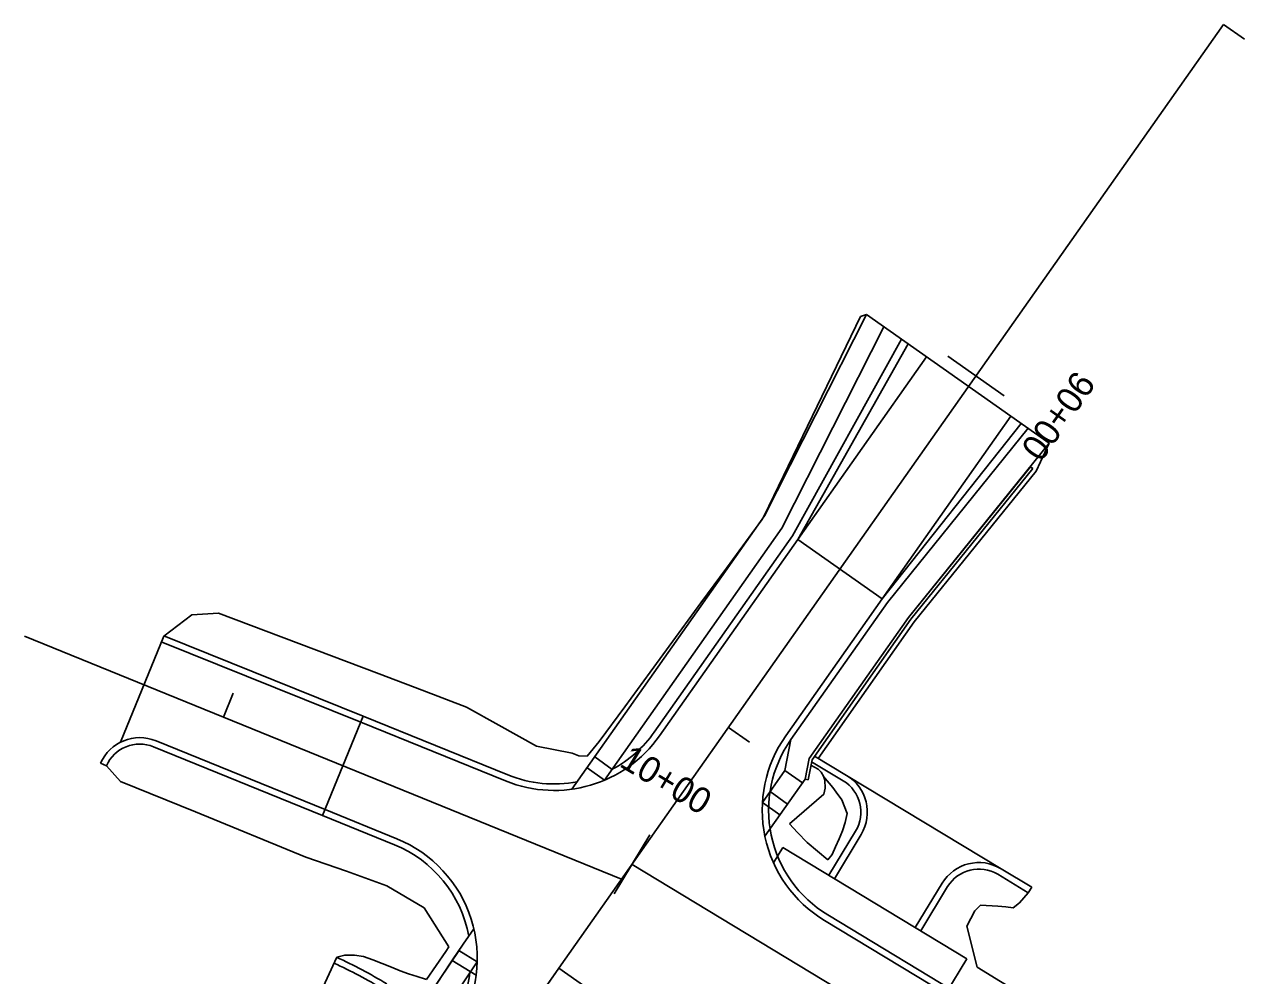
# Model space of a CAD drawing. Extents: x 979959 to 994833, y 1835619 to 1845316.
# Drawn here: x 982596.6 to 982880.5, y 1843464.2 to 1843685.5 of the extents above; entities that cross this region are included whole.
import ezdxf

# ---------------------------------------------------------------- set-up
doc = ezdxf.new("R2010")
doc.units = 0
for name, color, linetype in [('Concrete Walk Type Special', 7, 'Continuous'), ('R_Horz Alg', 7, 'Continuous'), ('R_Horz Alg Annot', 7, 'Continuous'), ('R_Horz Alg Stationing', 7, 'Continuous'), ('R_Horz Alg Stationing_Side Road', 7, 'Continuous'), ('R_Proposed Const Limits', 7, 'Continuous'), ('R_Proposed Road', 7, 'Continuous')]:
    doc.layers.add(name, color=color, linetype=linetype)

msp = doc.modelspace()

# ---------------------------------------------------------------- linework, layer by layer
at = {"layer": 'Concrete Walk Type Special'}
for p, q in [((982802.32, 1843547.54), (982830.67, 1843582.61)), ((982802.85, 1843547.14), (982831.19, 1843582.19)), ((982831.19, 1843582.19), (982830.67, 1843582.61)), ((982802.32, 1843547.54), (982779.22, 1843514.72)), ((982802.85, 1843547.14), (982779.85, 1843514.46)), ((982778.28, 1843509.91), (982779.22, 1843514.73)), ((982778.93, 1843509.79), (982779.85, 1843514.46)), ((982778.28, 1843509.91), (982778.93, 1843509.79))]:
    msp.add_line(p, q, dxfattribs=at)
at = {"layer": 'R_Horz Alg'}
for p, q in [((982875.58, 1843685.53), (982720.97, 1843465.93)), ((982596.63, 1843543.2), (982735.56, 1843486.65)), ((982737.99, 1843490.1), (982832.99, 1843432.69))]:
    msp.add_line(p, q, dxfattribs=at)
msp.add_arc((983167.15, 1843151.8), 545.67, 144.8526, 183.7353, dxfattribs=at)
at = {"layer": 'R_Horz Alg Annot'}
msp.add_line((982610.09, 1843308.44), (982720.97, 1843465.93), dxfattribs=at)
msp.add_lwpolyline([(982720.97, 1843465.93), (982827.27, 1843391.09)], dxfattribs=at)
at = {"layer": 'R_Horz Alg Stationing'}
for points in [[(982880.48, 1843682.07), (982875.58, 1843685.53)], [(982824.55, 1843599.15), (982811.47, 1843608.37)], [(982645.2, 1843529.91), (982642.94, 1843524.35)], [(982765.34, 1843518.54), (982760.44, 1843521.99)]]:
    msp.add_lwpolyline(points, dxfattribs=at)
at = {"layer": 'R_Horz Alg Stationing_Side Road'}
msp.add_lwpolyline([(982742.13, 1843496.95), (982733.85, 1843483.26)], dxfattribs=at)
at = {"layer": 'R_Proposed Const Limits'}
msp.add_line((982803.65, 1843546.53), (982781.26, 1843514.72), dxfattribs=at)
for points in [[(982792.51, 1843618.05), (982791.13, 1843617.54), (982768.75, 1843571.17)], [(982803.65, 1843546.53), (982831.97, 1843581.57), (982835.05, 1843588.09)], [(982768.75, 1843571.17), (982768.15, 1843570.3), (982765.85, 1843567.11), (982759.94, 1843559.04), (982754.02, 1843550.97), (982748.11, 1843542.9), (982746.01, 1843540.03), (982742.21, 1843534.83), (982736.28, 1843526.77), (982730.37, 1843518.71), (982727.51, 1843515.25)], [(982629.03, 1843543.24), (982635.56, 1843548.16), (982641.81, 1843548.58), (982679.18, 1843534.41), (982689.16, 1843530.62), (982699.51, 1843526.7), (982706.96, 1843522.49), (982715.76, 1843517.58)], [(982715.76, 1843517.58), (982724.09, 1843515.99), (982725.64, 1843515.34), (982727.51, 1843515.25)], [(982615.7, 1843513.03), (982619, 1843509.39), (982636.45, 1843502.31), (982662.07, 1843491.79), (982671.55, 1843488.54), (982680.96, 1843485.14), (982689.66, 1843479.99)], [(982779.6, 1843513.17), (982781.3, 1843512.26), (982781.98, 1843511.58), (982782.49, 1843510.66), (982782.8, 1843509.73), (982782.88, 1843507.82), (982782.57, 1843506.41), (982774.65, 1843499.57)], [(982783.51, 1843491.19), (982784.5, 1843492.37), (982785.32, 1843494.22), (982786.13, 1843496.06), (982786.92, 1843497.92), (982787.59, 1843499.85), (982788.04, 1843501.91), (982786.75, 1843505.1), (982785.48, 1843506.94), (982784.67, 1843507.98), (982782.51, 1843510.59)], [(982774.65, 1843499.57), (982776.48, 1843497.49), (982778.72, 1843495.21), (982783.51, 1843491.19)], [(982818.25, 1843466.21), (982815.83, 1843475.77), (982816.78, 1843477.53), (982817.74, 1843479.3), (982819.07, 1843480.65), (982823.09, 1843480.37), (982824.96, 1843480.2), (982826.68, 1843480), (982828.08, 1843481.19), (982830.17, 1843483.51)], [(982689.66, 1843479.99), (982695.38, 1843470.9)], [(982695.38, 1843470.9), (982694.68, 1843469.84), (982694.68, 1843469.84), (982690.14, 1843463.32)], [(982690.14, 1843463.32), (982689.91, 1843463.41), (982687.97, 1843464.06), (982685.97, 1843464.63), (982684.07, 1843465.35), (982682.06, 1843466.17), (982679.87, 1843467.02), (982677.69, 1843467.88), (982675.51, 1843468.7), (982673.42, 1843468.97), (982671.14, 1843469.02), (982669.27, 1843468.5)], [(982818.25, 1843466.21), (982823.68, 1843462.86), (982836.55, 1843455.18), (982844.3, 1843449.09), (982847, 1843445.5), (982849.17, 1843437.48)]]:
    msp.add_lwpolyline(points, dxfattribs=at)
at = {"layer": 'R_Proposed Road'}
for p, q in [((982792.51, 1843618.05), (982768.76, 1843571.17)), ((982796.56, 1843615.19), (982772.85, 1843568.29)), ((982800.64, 1843612.32), (982775.31, 1843566.56)), ((982802.25, 1843611.18), (982776.53, 1843565.7)), ((982806.47, 1843608.22), (982776.53, 1843565.7)), ((982826.09, 1843594.4), (982796.16, 1843551.88)), ((982828.54, 1843592.68), (982796.16, 1843551.88)), ((982830.13, 1843591.56), (982797.38, 1843551.02)), ((982802.29, 1843547.56), (982835.05, 1843588.09)), ((982768.76, 1843571.17), (982724.01, 1843507.6)), ((982772.85, 1843568.29), (982731.61, 1843509.71)), ((982775.31, 1843566.56), (982743.16, 1843520.9)), ((982776.53, 1843565.7), (982744.39, 1843520.04)), ((982796.16, 1843551.88), (982773.73, 1843520.02)), ((982797.38, 1843551.02), (982774.95, 1843519.16)), ((982802.29, 1843547.56), (982779.18, 1843514.74)), ((982629.03, 1843543.24), (982618.97, 1843518.53)), ((982628.47, 1843541.85), (982674.87, 1843523.23)), ((982629.03, 1843543.25), (982675.43, 1843524.62)), ((982675.44, 1843524.62), (982666.01, 1843501.47)), ((982675.44, 1843524.62), (982709.11, 1843510.91)), ((982674.87, 1843523.23), (982708.55, 1843509.52)), ((982627.24, 1843518.86), (982666.58, 1843502.85)), ((982773.53, 1843511.93), (982774.95, 1843519.16)), ((982626.68, 1843517.47), (982666.01, 1843501.47)), ((982614.32, 1843513.64), (982615.7, 1843513.03)), ((982729.29, 1843515.1), (982733.38, 1843512.22)), ((982778.24, 1843509.92), (982779.18, 1843514.74)), ((982787.12, 1843509.53), (982779.76, 1843513.98)), ((982787.9, 1843510.82), (982780.45, 1843515.32)), ((982727.52, 1843512.59), (982731.61, 1843509.71)), ((982773.53, 1843511.93), (982768.31, 1843504.51)), ((982773.53, 1843511.93), (982777.62, 1843509.05)), ((982823.84, 1843489.09), (982787.9, 1843510.82)), ((982778.24, 1843509.92), (982768.89, 1843496.64)), ((982768.31, 1843504.51), (982772.4, 1843501.63)), ((982770.08, 1843507.03), (982774.17, 1843504.15)), ((982666.58, 1843502.85), (982683.28, 1843496.06)), ((982666.01, 1843501.47), (982682.71, 1843494.67)), ((982783.77, 1843487.56), (982790, 1843497.86)), ((982785.05, 1843486.78), (982791.28, 1843497.09)), ((982770.9, 1843490.43), (982773.07, 1843494.02)), ((982773.07, 1843494.02), (982815.86, 1843468.16)), ((982823.06, 1843487.81), (982830.17, 1843483.51)), ((982823.84, 1843489.09), (982830.95, 1843484.8)), ((982803.88, 1843475.4), (982810.11, 1843485.71)), ((982805.17, 1843474.62), (982811.39, 1843484.93)), ((982830.95, 1843484.8), (982830.17, 1843483.51)), ((982782.74, 1843477.08), (982839.19, 1843442.96)), ((982783.52, 1843478.36), (982839.97, 1843444.24)), ((982669.27, 1843468.5), (982658.86, 1843445.77)), ((982701.71, 1843464.3), (982696.1, 1843467.71)), ((982701.96, 1843467.45), (982697.68, 1843470.05)), ((982810.95, 1843460.03), (982815.86, 1843468.16))]:
    msp.add_line(p, q, dxfattribs=at)
for points in [[(982835.05, 1843588.09), (982792.51, 1843618.05)], [(982796.16, 1843551.88), (982776.53, 1843565.7)]]:
    msp.add_lwpolyline(points, dxfattribs=at)
for centre, radius, start, end in [((982623.47, 1843509.6), 10, 67.8526, 156.1903), ((982719.86, 1843537.31), 30, 247.8526, 324.8526), ((982719.86, 1843537.31), 28.5, 298.3273, 324.8526), ((982798.26, 1843502.75), 30, 144.8526, 238.8526), ((982798.26, 1843502.75), 28.5, 144.8526, 238.8526), ((982623.47, 1843509.6), 8.5, 67.8526, 156.1903), ((982719.86, 1843537.31), 28.5, 247.8526, 280.8492), ((982782.72, 1843502.26), 10, 328.8526, 58.8526), ((982782.72, 1843502.26), 8.5, 328.8526, 58.8526), ((982671.97, 1843468.27), 30, 327.4171, 67.8526), ((982671.97, 1843468.27), 28.5, 10.4468, 67.8526), ((982818.67, 1843480.53), 10, 58.8526, 148.8526), ((982818.67, 1843480.53), 8.5, 58.8526, 148.8526), ((983167.15, 1843151.8), 567.17, 145.2433, 173.5095), ((983167.15, 1843151.8), 567.17, 145.8418, 173.5095), ((983167.15, 1843151.8), 562.17, 145.8418, 174.8356), ((982622.45, 1843366.2), 112.5, 58.6781, 65.4099), ((982622.45, 1843366.2), 111, 58.6781, 65.4099), ((982671.97, 1843468.27), 28.5, 327.4171, 353.3151)]:
    msp.add_arc(centre, radius, start, end, dxfattribs=at)

# ---------------------------------------------------------------- texts
at = {"layer": 'R_Horz Alg Stationing'}
msp.add_text('90+00', height=6, rotation=234.8526, dxfattribs=at).set_placement((982841.16, 1843605.37))
at = {"layer": 'R_Horz Alg Stationing_Side Road'}
msp.add_text('10+00', height=6, rotation=328.8526, dxfattribs=at).set_placement((982734.76, 1843513.08))

doc.saveas('drawing.dxf')
